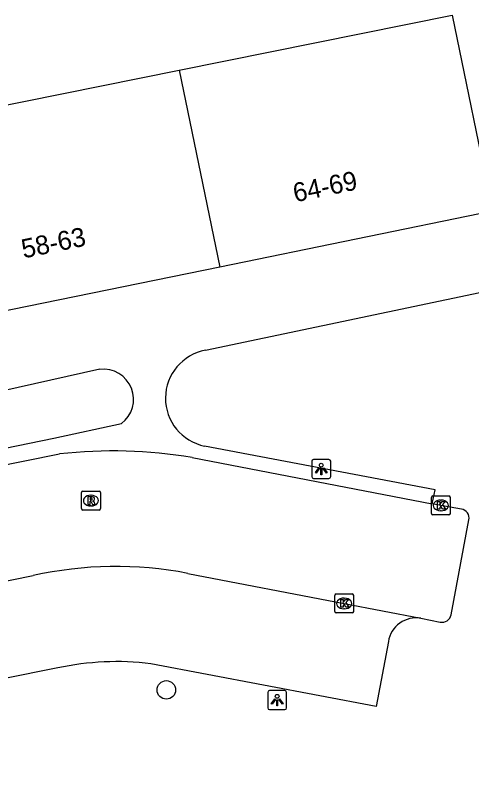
# Model space of a CAD drawing. Extents: x 162250 to 162654, y 380744 to 381605.
# Drawn here: x 162593.35 to 162617.45, y 380832.81 to 380872.69 of the extents above; entities that cross this region are included whole.
import ezdxf

# ---------------------------------------------------------------- set-up
doc = ezdxf.new("R2010")
doc.units = 0
for name, color, linetype in [('IMGEO_Boom', 7, 'Continuous'), ('IMGEO_Kolk', 7, 'Continuous'), ('IMGEO_Lichtpunt', 7, 'Continuous'), ('IMGEO_Pand', 7, 'Continuous'), ('IMGEO_Pand_nummerreeks', 7, 'Continuous'), ('IMGEO_Parkeervlak_open', 7, 'Continuous'), ('IMGEO_Rijbaan_lokaal_open', 7, 'Continuous'), ('IMGEO_Rioolput', 7, 'Continuous'), ('IMGEO_Voetpad_open', 7, 'Continuous')]:
    doc.layers.add(name, color=color, linetype=linetype)

msp = doc.modelspace()

# ---------------------------------------------------------------- linework, layer by layer
at = {"layer": 'IMGEO_Boom'}
msp.add_circle((162601.328, 380837.083), 0.489, dxfattribs=at)
at = {"layer": 'IMGEO_Kolk'}
for p, q in [((162615.316, 380846.392), (162615.316, 380847.244)), ((162615.391, 380847.318), (162616.243, 380847.318)), ((162616.317, 380847.244), (162616.317, 380846.392)), ((162615.804, 380847.098), (162615.829, 380847.098)), ((162615.827, 380846.538), (162615.802, 380846.538)), ((162616.243, 380846.318), (162615.391, 380846.318)), ((162610.214, 380841.219), (162610.214, 380842.071)), ((162610.289, 380842.145), (162611.141, 380842.145)), ((162611.215, 380842.071), (162611.215, 380841.219)), ((162610.702, 380841.925), (162610.727, 380841.925)), ((162610.725, 380841.365), (162610.7, 380841.365)), ((162611.141, 380841.145), (162610.289, 380841.145))]:
    msp.add_line(p, q, dxfattribs=at)
for points in [[(162615.316, 380846.392), (162615.316, 380847.244)], [(162615.391, 380847.318), (162616.243, 380847.318)], [(162616.317, 380847.244), (162616.317, 380846.392)], [(162615.637, 380847.018), (162615.76, 380847.018), (162615.76, 380846.867), (162615.89, 380847.018), (162616.054, 380847.018), (162615.908, 380846.867), (162616.061, 380846.618), (162615.909, 380846.618), (162615.824, 380846.782), (162615.76, 380846.715), (162615.76, 380846.618), (162615.637, 380846.618), (162615.637, 380847.018)], [(162616.243, 380846.318), (162615.391, 380846.318)], [(162610.214, 380841.219), (162610.214, 380842.071)], [(162610.289, 380842.145), (162611.141, 380842.145)], [(162611.215, 380842.071), (162611.215, 380841.219)], [(162610.535, 380841.845), (162610.658, 380841.845), (162610.658, 380841.694), (162610.788, 380841.845), (162610.952, 380841.845), (162610.806, 380841.694), (162610.959, 380841.445), (162610.807, 380841.445), (162610.722, 380841.609), (162610.658, 380841.542), (162610.658, 380841.445), (162610.535, 380841.445), (162610.535, 380841.845)], [(162611.141, 380841.145), (162610.289, 380841.145)]]:
    msp.add_lwpolyline(points, dxfattribs=at)
for centre, start, end in [((162615.393, 380847.242), 91.552, 178.448), ((162615.393, 380847.242), 91.552, 178.448), ((162616.241, 380847.242), 1.552, 88.448), ((162616.241, 380847.242), 1.552, 88.448), ((162615.393, 380846.394), 181.552, 268.448), ((162615.393, 380846.394), 181.552, 268.448), ((162616.241, 380846.394), 271.552, 358.448), ((162616.241, 380846.394), 271.552, 358.448), ((162610.291, 380842.069), 91.552, 178.448), ((162610.291, 380842.069), 91.552, 178.448), ((162611.139, 380842.069), 1.552, 88.448), ((162611.139, 380842.069), 1.552, 88.448), ((162610.291, 380841.221), 181.552, 268.448), ((162610.291, 380841.221), 181.552, 268.448), ((162611.139, 380841.221), 271.552, 358.448), ((162611.139, 380841.221), 271.552, 358.448)]:
    msp.add_arc(centre, 0.0765, start, end, dxfattribs=at)
for centre, major_axis, ratio, start_param, end_param in [((162615.803, 380846.818), (-0.387, 0.002), 0.722429, 4.712389, 7.853982), ((162615.828, 380846.818), (-0.39, 0.002), 0.717154, 1.570796, 4.712389), ((162610.701, 380841.645), (-0.387, 0.002), 0.722429, 4.712389, 7.853982), ((162610.726, 380841.645), (-0.39, 0.002), 0.717154, 1.570796, 4.712389)]:
    msp.add_ellipse(centre, major_axis=major_axis, ratio=ratio, start_param=start_param, end_param=end_param, dxfattribs=at)
at = {"layer": 'IMGEO_Lichtpunt'}
for p, q in [((162609.908, 380849.241), (162609.1, 380849.241)), ((162609.908, 380849.241), (162609.1, 380849.241)), ((162609.006, 380849.146), (162609.006, 380848.339)), ((162609.006, 380849.146), (162609.006, 380848.339)), ((162610.002, 380848.339), (162610.002, 380849.146)), ((162610.002, 380848.339), (162610.002, 380849.146)), ((162609.1, 380848.245), (162609.908, 380848.245)), ((162609.1, 380848.245), (162609.908, 380848.245)), ((162606.681, 380836.949), (162606.681, 380836.142)), ((162606.681, 380836.949), (162606.681, 380836.142)), ((162607.583, 380837.044), (162606.775, 380837.044)), ((162607.583, 380837.044), (162606.775, 380837.044)), ((162607.677, 380836.142), (162607.677, 380836.949)), ((162607.677, 380836.142), (162607.677, 380836.949)), ((162606.775, 380836.048), (162607.583, 380836.048)), ((162606.775, 380836.048), (162607.583, 380836.048))]:
    msp.add_line(p, q, dxfattribs=at)
for points in [[(162609.38, 380848.81), (162609.419, 380848.782), (162609.231, 380848.52), (162609.193, 380848.547), (162609.38, 380848.81)], [(162609.482, 380848.762), (162609.529, 380848.762), (162609.529, 380848.44), (162609.482, 380848.44), (162609.482, 380848.762)], [(162609.592, 380848.782), (162609.63, 380848.809), (162609.817, 380848.547), (162609.778, 380848.519), (162609.592, 380848.782)], [(162607.055, 380836.613), (162607.094, 380836.585), (162606.906, 380836.323), (162606.868, 380836.35), (162607.055, 380836.613)], [(162607.157, 380836.565), (162607.204, 380836.565), (162607.204, 380836.243), (162607.157, 380836.243), (162607.157, 380836.565)], [(162607.267, 380836.585), (162607.305, 380836.612), (162607.492, 380836.35), (162607.453, 380836.322), (162607.267, 380836.585)]]:
    msp.add_lwpolyline(points, dxfattribs=at)
for centre in [(162609.505, 380848.944), (162607.18, 380836.747)]:
    msp.add_circle(centre, 0.0994, dxfattribs=at)
for centre, start, end in [((162609.1, 380849.146), 90, 180), ((162609.1, 380849.146), 90, 180), ((162609.908, 380849.146), 0, 90), ((162609.908, 380849.146), 0, 90), ((162609.1, 380848.339), 180, 270), ((162609.1, 380848.339), 180, 270), ((162609.908, 380848.339), 270, 0), ((162609.908, 380848.339), 270, 360), ((162606.775, 380836.949), 90, 180), ((162606.775, 380836.949), 90, 180), ((162607.583, 380836.949), 0, 90), ((162607.583, 380836.949), 0, 90), ((162606.775, 380836.142), 180, 270), ((162606.775, 380836.142), 180, 270), ((162607.583, 380836.142), 270, 0), ((162607.583, 380836.142), 270, 360)]:
    msp.add_arc(centre, 0.0946, start, end, dxfattribs=at)
at = {"layer": 'IMGEO_Pand'}
for points in [[(162602.001, 380869.784), (162616.411, 380872.69), (162618.544, 380862.342)], [(162587.591, 380866.878), (162602.001, 380869.784)], [(162602.001, 380869.784), (162604.143, 380859.394)], [(162618.544, 380862.342), (162604.143, 380859.394)], [(162604.143, 380859.394), (162589.741, 380856.447)]]:
    msp.add_lwpolyline(points, dxfattribs=at)
at = {"layer": 'IMGEO_Parkeervlak_open'}
for points in [[(162613.048, 380839.636), (162612.406, 380836.21), (162600.51, 380838.466)], [(162595.594, 380838.244), (162569.268, 380832.961), (162568.517, 380832.81)]]:
    msp.add_lwpolyline(points, dxfattribs=at)
for centre, radius, start, end in [((162614.515, 380839.396), 1.486, 80.4672, 170.7157), ((162598.71, 380823.793), 14.783, 83.005, 102.1663)]:
    msp.add_arc(centre, radius, start, end, dxfattribs=at)
at = {"layer": 'IMGEO_Rijbaan_lokaal_open'}
for points in [[(162564.132, 380843.173), (162568.317, 380844.003), (162588.525, 380848.096), (162595.697, 380849.533)], [(162602.692, 380849.343), (162615.367, 380846.905)], [(162616.902, 380846.627), (162615.817, 380846.818), (162615.367, 380846.905)], [(162616.36, 380841.046), (162617.302, 380846.05)], [(162566.221, 380837.416), (162594.293, 380843.113)], [(162602.462, 380843.231), (162610.715, 380841.645), (162614.761, 380840.862)], [(162614.761, 380840.862), (162615.777, 380840.665)]]:
    msp.add_lwpolyline(points, dxfattribs=at)
for centre, radius, start, end in [((162598.528, 380824.899), 24.796, 80.3325, 96.5557), ((162616.82, 380846.143), 0.491, 349.1261, 80.3364), ((162598.662, 380823.474), 20.12, 79.1132, 102.5419), ((162615.88, 380841.144), 0.49, 257.8966, 348.434)]:
    msp.add_arc(centre, radius, start, end, dxfattribs=at)
at = {"layer": 'IMGEO_Rioolput'}
for p, q in [((162596.848, 380846.647), (162596.848, 380847.499)), ((162596.923, 380847.573), (162597.775, 380847.573)), ((162597.336, 380847.353), (162597.361, 380847.353)), ((162597.849, 380847.499), (162597.849, 380846.647)), ((162597.775, 380846.573), (162596.923, 380846.573)), ((162597.359, 380846.793), (162597.334, 380846.793))]:
    msp.add_line(p, q, dxfattribs=at)
for points in [[(162596.848, 380846.647), (162596.848, 380847.499)], [(162596.923, 380847.573), (162597.775, 380847.573)], [(162597.437, 380847.271), (162597.185, 380847.273), (162597.185, 380846.873)], [(162597.849, 380847.499), (162597.849, 380846.647)], [(162597.185, 380846.873), (162597.309, 380846.873), (162597.309, 380847.035), (162597.32, 380847.035)], [(162597.363, 380847.192), (162597.309, 380847.192), (162597.309, 380847.111)], [(162597.309, 380847.111), (162597.361, 380847.111)], [(162597.367, 380847.006), (162597.438, 380846.873), (162597.578, 380846.873), (162597.513, 380846.999)], [(162597.775, 380846.573), (162596.923, 380846.573)]]:
    msp.add_lwpolyline(points, dxfattribs=at)
for centre, radius, start, end in [((162596.925, 380847.497), 0.0765, 91.552, 178.448), ((162596.925, 380847.497), 0.0765, 91.552, 178.448), ((162597.436, 380847.161), 0.109, 350.3612, 89.416), ((162597.773, 380847.497), 0.0765, 1.552, 88.448), ((162597.773, 380847.497), 0.0765, 1.552, 88.448), ((162597.319, 380846.982), 0.0533, 26.0293, 88.6989), ((162597.345, 380847.3), 0.19, 274.7715, 282.9687), ((162597.369, 380847.096), 0.0964, 77.0061, 93.1865), ((162597.383, 380847.153), 0.0378, 276.6634, 79.6772), ((162597.434, 380847.161), 0.112, 277.5842, 350.9817), ((162597.418, 380846.946), 0.108, 29.5134, 73.7905), ((162596.925, 380846.649), 0.0765, 181.552, 268.448), ((162596.925, 380846.649), 0.0765, 181.552, 268.448), ((162597.773, 380846.649), 0.0765, 271.552, 358.448), ((162597.773, 380846.649), 0.0765, 271.552, 358.448)]:
    msp.add_arc(centre, radius, start, end, dxfattribs=at)
for centre, major_axis, ratio, start_param, end_param in [((162597.335, 380847.073), (-0.387, 0.002), 0.722429, 4.712389, 7.853982), ((162597.36, 380847.073), (-0.39, 0.002), 0.717154, 1.570796, 4.712389)]:
    msp.add_ellipse(centre, major_axis=major_axis, ratio=ratio, start_param=start_param, end_param=end_param, dxfattribs=at)
at = {"layer": 'IMGEO_Voetpad_open'}
for points in [[(162603.392, 380855.005), (162619.217, 380858.339), (162621.589, 380858.795)], [(162597.818, 380853.999), (162588.47, 380851.918), (162585.709, 380851.358)], [(162586.391, 380848.516), (162595.392, 380850.372), (162598.958, 380851.134)], [(162615.367, 380846.905), (162615.515, 380847.643), (162603.351, 380849.948)]]:
    msp.add_lwpolyline(points, dxfattribs=at)
for centre, radius, start, end in [((162603.858, 380852.473), 2.575, 100.4233, 258.6477), ((162598, 380852.412), 1.597, 306.8658, 96.53)]:
    msp.add_arc(centre, radius, start, end, dxfattribs=at)

# ---------------------------------------------------------------- texts
at = {"layer": 'IMGEO_Pand_nummerreeks'}
for s, rotation, p in [('64-69', 11.6949, (162608.127, 380862.809)), ('58-63', 11.6313, (162593.793, 380859.849))]:
    msp.add_text(s, height=1, rotation=rotation, dxfattribs=at).set_placement(p)

doc.saveas('drawing.dxf')
